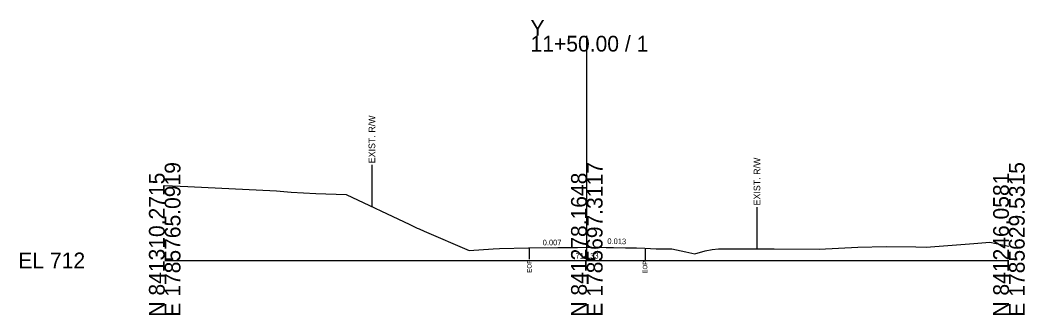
# Model space of a CAD drawing. Extents: x -26 to 153, y 990 to 3546.
# Drawn here: x -25.7 to 152.8, y 2990.3 to 3042.7 of the extents above; entities that cross this region are included whole.
import ezdxf

# ---------------------------------------------------------------- set-up
doc = ezdxf.new("R2010")
doc.units = 0
for name, color, linetype in [('Exist Cross Section Cell', 7, 'Continuous'), ('Exist XS Center Line Elevation Label', 7, 'Continuous'), ('Exist XS Ground Line', 7, 'Continuous'), ('Old_Level_10', 7, 'Continuous'), ('Scratch_Level_1', 7, 'Continuous')]:
    doc.layers.add(name, color=color, linetype=linetype)

msp = doc.modelspace()

# ---------------------------------------------------------------- linework, layer by layer
at = {"layer": 'Exist Cross Section Cell'}
for p, q in [((75, 3000), (75, 3039.94)), ((0, 3000), (75, 3000)), ((75, 3000), (150, 3000))]:
    msp.add_line(p, q, dxfattribs=at)
at = {"layer": 'Exist XS Ground Line'}
msp.add_lwpolyline([(0, 3013.31), (4.11, 3013.13), (19.89, 3012.38), (22.46, 3012.14), (26.83, 3011.92), (32.22, 3011.73), (43.53, 3006.4), (44.88, 3005.75), (45.2, 3005.63), (46.08, 3005.23), (54.08, 3001.77), (58.38, 3002.03), (59.48, 3002.09), (64.66, 3002.26), (73.32, 3002.31), (75, 3002.33), (75.69, 3002.34), (83.8, 3002.21), (85.3, 3002.2), (87.35, 3002.07), (90.08, 3002.05), (92.62, 3001.51), (94.17, 3001.18), (96.05, 3001.68), (97.29, 3001.95), (98.41, 3002.03), (106.85, 3002.08), (108.27, 3002.05), (116.26, 3002.02), (123.15, 3002.38), (128.21, 3002.5), (133.48, 3002.43), (135.33, 3002.38), (136.07, 3002.43), (143.76, 3003.02), (146.63, 3003.22), (150, 3002.53)], dxfattribs=at)
at = {"layer": 'Old_Level_10'}
for p, q in [((36.81, 3016.97), (36.81, 3009.57)), ((105.23, 3009.47), (105.23, 3002.07)), ((64.78, 3002.26), (64.78, 3000.21)), ((85.34, 3002.11), (85.34, 3000.06))]:
    msp.add_line(p, q, dxfattribs=at)
at = {"layer": 'Scratch_Level_1'}
for p, q in [((64.66, 3002.26), (75, 3002.33)), ((75, 3002.33), (85.3, 3002.2))]:
    msp.add_line(p, q, dxfattribs=at)

# ---------------------------------------------------------------- texts
at = {"layer": 'Exist Cross Section Cell'}
for s, p in [('Y', (65, 3039.94)), ('11+50.00 / 1', (65, 3037.14)), ('EL 712', (-26, 2998.6))]:
    msp.add_text(s, height=2.8, dxfattribs=at).set_placement(p)
for s, p in [('E 1785765.0919', (2.8, 2990)), ('E 1785697.3117', (77.8, 2990)), ('E 1785629.5315', (152.8, 2990)), ('N 841310.2715', (0, 2990)), ('N 841278.1648', (75, 2990)), ('N 841246.0581', (150, 2990))]:
    msp.add_text(s, height=2.8, rotation=90, dxfattribs=at).set_placement(p)
at = {"layer": 'Exist XS Center Line Elevation Label'}
msp.add_text('714.33', height=1, dxfattribs=at).set_placement((73, 3000.33))
at = {"layer": 'Old_Level_10'}
for s, height, p in [('EXIST. R/W', 1.181, (37.4, 3017.27)), ('EXIST. R/W', 1.181, (105.82, 3009.77)), ('EOP', 0.787, (65.18, 2997.81)), ('EOP', 0.787, (85.74, 2997.66))]:
    msp.add_text(s, height=height, rotation=90, dxfattribs=at).set_placement(p)
at = {"layer": 'Scratch_Level_1'}
for s, rotation, p in [('0.007', 0.417, (67.16, 3002.67)), ('0.013', 359.2612, (78.64, 3002.92))]:
    msp.add_text(s, height=1, rotation=rotation, dxfattribs=at).set_placement(p)

doc.saveas('drawing.dxf')
